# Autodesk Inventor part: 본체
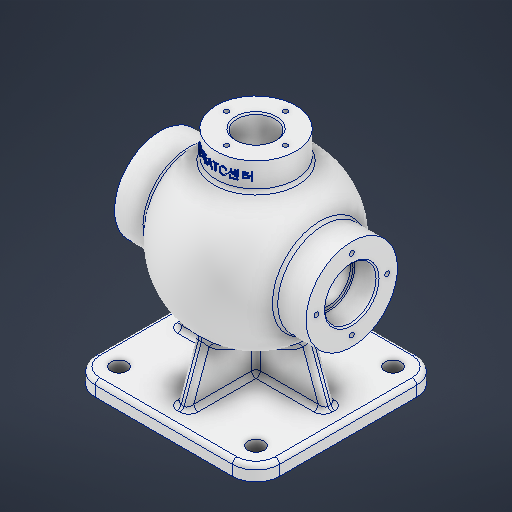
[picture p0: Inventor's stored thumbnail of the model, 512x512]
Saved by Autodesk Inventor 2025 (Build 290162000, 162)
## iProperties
Created: 2025-08
Part Number: 본체
Material: 알루미늄 6061
Document SubType Name: Modeling
Designer: infra14
Density: 2.7 g/cm^3
Appearance: 알루미늄 - 평지
Mass: 1526.72 g
Surface Area: 1173.82 cm^2
Volume: 565.453 cm^3
Author: infra14
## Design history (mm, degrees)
sketch "스케치1"
  geometry: L1 (-46.5, 62.5)-(46.5, 62.5); L2 (62.5, 46.5)-(62.5, -46.5); L3 (46.5, -62.5)-(-46.5, -62.5); L4 (-62.5, -46.5)-(-62.5, 46.5); L5 (-62.5, 62.5)-(62.5, -62.5); L6 (62.5, 62.5)-(-62.5, -62.5); A1 r 16 centre (46.5, 46.5) between (62.5, 46.5) and (46.5, 62.5); A2 r 16 centre (46.5, -46.5) between (46.5, -62.5) and (62.5, -46.5); A3 r 16 centre (-46.5, -46.5) between (-62.5, -46.5) and (-46.5, -62.5); A4 r 16 centre (-46.5, 46.5) between (-46.5, 62.5) and (-62.5, 46.5); 1 further point
  constraints: 12 end point, 8 point on circle, 8 point on line, 8 tangent, 4 centre point, 3 equal radius, 2 midpoint, 2 parallel, 1 horizontal, 1 perpendicular
  dimensions: "d0" = 125 distance of L6.end L5.start; "d1" = 125 distance of L5.end L6.end; "d2" = 16 radius of A1
extrude "돌출1" new body sketch "스케치1" distance "d3" = 10; taper "d4" = 0 deg
sketch "스케치2"
  geometry: L1 (46.5, 0)-(-46.5, 0) reference; L2 (65, 54)-(-65, 54); L3 (-65, 54)-(-65, 116); L4 (-65, 116)-(65, 116); L5 (65, 116)-(65, 54); L6 (65, 54)-(-65, 116); L7 (-65, 54)-(65, 116); L8 (65, 85)-(-65, 85); C1 r 54 at (0, 85); C2 r 44 at (0, 85); 6 further points
  constraints: 14 end point, 5 midpoint, 2 centre point, 2 parallel, 1 coincident, 1 horizontal, 1 perpendicular, 1 vertical alignment
  dimensions: "d5" = 108 diameter of C1; "d6" = 88 diameter of C2; "d7" = 85 distance from line of L1 C1.centre; "d8" = 62 distance between parallel lines of L2 L4; "d9" = 130 distance between parallel lines of L5 L3
revolve "회전1" stored, may be unused: angle "d10" = 90 deg
sketch "스케치3"
  geometry: L1 (-46.5, 10)-(46.5, 10) reference; L2 (50.5, 10)-(30.482, 65); L3 (30.482, 65)-(-30.482, 65); L4 (-30.482, 65)-(-50.5, 10); L5 (62.5, 0)-(62.5, 10) reference; L6 (-62.5, 0)-(-62.5, 10) reference; L7 (-46.5, 0)-(46.5, 0) reference; 1 further point
  constraints: 6 end point, 2 point on line, 1 parallel
  dimensions: "d11" = 12 distance from line of L5 L2.start; "d12" = 12 distance from line of L6 L4.end; "d13" = 20 deg angle of L5 L2; "d14" = 20 deg angle of L6 L4; "d15" = 65 distance between parallel lines of L7 L3
feature "리브1" sketch "스케치3" dims "d16" = 1, "d17" = 8, "d18" = 0, "d19" = 0, "d20" = 1, "d21" = 1
sketch "스케치4"
  geometry: L1 (10, -46.5)-(10, 46.5) reference; L2 (10, 50.5)-(65, 30.482); L3 (65, 30.482)-(65, -30.482); L4 (65, -30.482)-(10, -50.5); L5 (0, 62.5)-(10, 62.5) reference; L6 (0, -62.5)-(10, -62.5) reference; L7 (0, -46.5)-(0, 46.5) reference; 1 further point
  constraints: 6 end point, 2 point on line, 1 vertical
  dimensions: "d22" = 12 distance from line of L5 L2.start; "d23" = 12 distance from line of L6 L4.end; "d24" = 20 deg angle of L5 L2; "d25" = 20 deg angle of L6 L4; "d26" = 65 distance between parallel lines of L7 L3
feature "리브2" sketch "스케치4" dims "d27" = 1, "d28" = 8, "d29" = 0, "d30" = 0, "d31" = 1, "d32" = 1
sketch "스케치5"
  geometry: L1 (-65, 116)-(-65, 54) reference; L2 (-64, 102.5)-(-49.6, 102.5); L3 (-49, 101.9)-(-49, 100); L4 (-49, 100)-(-41.364, 100); L5 (-41.364, 100)-(-41.364, 85); L6 (-44.215, 116)-(-44.215, 54) reference; L7 (-41.364, 85)-(-65, 85); L8 (-65, 85)-(-65, 102.5); L9 (-65, 54)-(-65, 116) reference; L10 (-65, 103.5)-(-65, 116); L11 (-64, 102.5)-(-65, 103.5); A1 r 0.6 centre (-49.6, 101.9) between (-49, 101.9) and (-49.6, 102.5); 8 further points
  constraints: 16 end point, 5 point on line, 4 perpendicular, 2 point on circle, 2 tangent, 1 centre point, 1 collinear, 1 horizontal, 1 horizontal alignment, 1 midpoint, 1 parallel, 2 other
  dimensions: "d33" = 15 distance from line of L7 point (-45.182, 100); "d34" = 17.5 distance between parallel lines of L7 L2; "d35" = 16 distance of L8.end point (-49, 102.5); "d36" = 0.6 radius of A1; "d37" = 1 distance of L2.start L8.end; "d38" = 45 deg angle of L2 L11
revolve "회전2" sketch "스케치5" stored, may be unused: angle "d39" = 90 deg
sketch "스케치6"
  geometry: L1 (0, 0)-(0, 24); C1 r 18.5 at (0, 0) reference; C2 r 31 at (0, 0) reference; C3 r 15 at (0, 0) reference; 5 further points
  constraints: 2 end point, 1 coincident, 1 vertical, 5 other
  dimensions: "d40" = 24 distance of L1.start L1.end; "d43" = 360 deg dimension on C1.centre point (0, 24) (derived)
hole "구멍1" sketch "스케치6" at (0, 24), (-24, 0), (0, -24), (24, 0) diameter "d45" = 3.242; stored, may be unused: countersink angle "d49" = 90 deg, drill point angle "d51" = 118 deg; dims "d46" = 12, "d47" = 4, "d48" = 2, "d50" = 15
sketch "스케치7"
  geometry: C1 r 1.621 at (24, 0) reference; C2 r 1.621 at (0, -24) reference; C3 r 1.621 at (-24, 0) reference; C4 r 1.621 at (0, 24) reference; C5 r 18.5 at (0, 0) reference; C6 r 31 at (0, 0) reference; C7 r 15 at (0, 0) reference; C8 r 15 at (0, 0); 1 further point
  constraints: 1 centre point, 1 coincident
  dimensions: "d52" = 30 diameter of C8
extrude "돌출2" cut sketch "스케치7" extent not by distance; stored distance "d53" = 0; taper "d54" = 0 deg
sketch "스케치8"
  geometry: 1 further point
revolve "회전3" stored, may be unused: angle "d55" = 90 deg
node "작업 평면1"
sketch "스케치9"
  geometry: C1 r 27 at (0, 0); 1 further point
  constraints: 1 centre point, 1 coincident
  dimensions: "d57" = 54 diameter of C1
extrude "돌출3" join sketch "스케치9" stored distance "d58" = 10; taper "d59" = 0 deg
sketch "스케치10"
  geometry: C1 r 27 at (0, 0) reference; C2 r 13 at (0, 0); 1 further point
  constraints: 1 centre point, 1 coincident
  dimensions: "d60" = 26 diameter of C2
extrude "돌출4" cut sketch "스케치10" stored distance "d61" = 0; taper "d62" = 0 deg
sketch "스케치11"
  geometry: L1 (0, 0)-(0, -20); C1 r 13 at (0, 0) reference; 5 further points
  constraints: 2 end point, 1 coincident, 1 vertical, 5 other
  dimensions: "d63" = 20 distance of L1.start L1.end; "d66" = 360 deg dimension on point (0, 0) point (0, -20) (derived)
hole "구멍2" sketch "스케치11" at (0, -20), (20, 0), (0, 20), (-20, 0) diameter "d68" = 3.242; stored, may be unused: countersink angle "d72" = 90 deg, drill point angle "d74" = 118 deg; dims "d69" = 9, "d70" = 4, "d71" = 2, "d73" = 11
chamfer "모따기1" distance "d75" = 1; stored, may be unused: second distance "d76" = 2, angle "d77" = 45 deg
node "작업 평면2"
sketch "스케치12"
  geometry: L1 (-12.324, 143.035)-(12.324, 143.035); L2 (12.324, 143.035)-(12.324, 138.965); L3 (12.324, 138.965)-(-12.324, 138.965); L4 (-12.324, 138.965)-(-12.324, 143.035); L5 (-27, 150)-(27, 150) reference; 4 further points
  constraints: 3 midpoint, 1 vertical alignment, 2 other
  dimensions: "d79" = 9 distance from line of point (-12.324, 141) L5
feature "엠보싱1" sketch "스케치12" dims "d0" = 125, "d1" = 125, "d2" = 16, "d80" = 0.5, "d81" = 0
sketch "스케치13"
  geometry: L1 (-46.5, -46.5)-(46.5, -46.5); L2 (46.5, -46.5)-(46.5, 46.5); L3 (46.5, 46.5)-(-46.5, 46.5); L4 (-46.5, 46.5)-(-46.5, -46.5); L5 (-46.5, -46.5)-(46.5, 46.5); L6 (46.5, -46.5)-(-46.5, 46.5); C1 r 13 at (0, 0) reference; 5 further points
  constraints: 12 end point, 4 coincident, 2 midpoint, 2 parallel, 1 horizontal, 1 perpendicular
  dimensions: "d82" = 93 distance of L2.end L3.end; "d83" = 93 distance of L1.end L2.end
hole "구멍3" sketch "스케치13" at (-46.5, 46.5), (46.5, 46.5), (46.5, -46.5), (-46.5, -46.5) diameter "d84" = 11; stored, may be unused: countersink angle "d88" = 90 deg, drill point angle "d90" = 118 deg; dims "d85" = 9, "d86" = 4, "d87" = 2, "d89" = 11
fillet "모깎기1" dims "d91" = 3
fillet "모깎기2" dims "d92" = 3
fillet "모깎기3" dims "d93" = 3
fillet "모깎기4" dims "d94" = 3
feature "ҋ耀ҍ耀ҏ耀ґ耀ғ耀ҕ耀җ耀ҙ耀" dims "d0" = 125, "d1" = 125, "d2" = 16, "d3" = 10, "d4" = 0, "d5" = 108, "d6" = 88, "d7" = 85, "d8" = 62, "d9" = 130, "d10" = 90 deg, "d11" = 12, "d12" = 12, "d13" = 20 deg, "d14" = 20 deg, "d15" = 65, "d16" = 1, "d17" = 8, "d18" = 0, "d19" = 0, "d20" = 1, "d21" = 1, "d22" = 12, "d23" = 12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
node "솔리드1"
mirror "미러1"
node "투영된 루프1"
node "스케치 - 원형 패턴1" dims "d43" = 360 deg (derived)
node "투영된 루프2"
node "투영된 루프3"
node "스케치 - 원형 패턴2" dims "d66" = 360 deg (derived)
feature "A9D066F2-1C7D-4E18-AEED-F7BC21143FA4" dims "d84" = 11, "d85" = 9, "d86" = 4, "d87" = 2, "d88" = 90 deg, "d89" = 11, "d90" = 118 deg
